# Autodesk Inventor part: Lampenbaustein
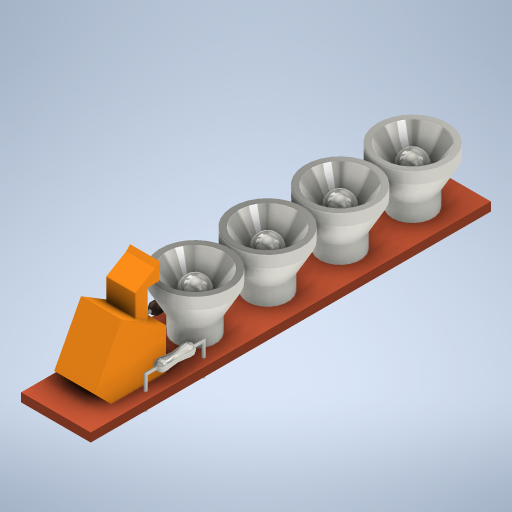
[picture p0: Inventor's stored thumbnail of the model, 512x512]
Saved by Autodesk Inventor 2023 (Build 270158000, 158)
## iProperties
Created: 2023-11
Part Number: Lampenbaustein
Material: Generisch
Document SubType Name: Modeling
Designer: Admin
Density: 1 g/cm^3
Appearance: Vorgabe
Author: Admin
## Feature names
1. Extrusion1
2. Extrusion2
3. Extrusion3
4. Extrusion4
5. Umdrehung1 [Revolution]
6. Extrusion5
7. Rechteckige Anordnung2 [Rectangular Pattern]
8. Umdrehung2 [Revolution]
9. Sweeping1
## Parameters: d0 = 12 mm, d1 = 69 mm, d2 = 1.5 mm, d3 = 0, d4 = 9 mm, d6 = 4 mm, d7 = 12.3 mm, d8 = 7 mm, d9 = 11.7 mm, d10 = 19 mm, d11 = 7 mm, d12 = 0, d13 = 3.8 mm, d16 = 2 mm, d17 = 2.5 mm, d18 = 2.2 mm, d19 = 1 mm, d20 = 4 mm, d21 = 15.5 mm, d22 = 3 mm, d23 = 5 mm, d24 = 0, d25 = 0.5 mm, d26 = 2.54 mm, d27 = 5 mm, d28 = 2.5 mm, d29 = 4 mm, d30 = 0, d31 = 3.5 mm, d32 = 2.25 mm, d33 = 6 mm, d34 = 1 mm, d35 = 1 mm, d36 = 4 mm, d37 = 2 mm, d38 = 9.5 mm, d39 = 10.5 mm, d40 = 3 mm, d41 = 90 deg, d45 = 0.25 mm, d46 = 2.54 mm, d47 = 4 mm, d48 = 0, d51 = 12.5 mm, d52 = 2.5 mm, d53 = 0.75 mm, d54 = 6.5 mm, d55 = 1 mm, d56 = 10.5 mm, d57 = 4.5 mm, d58 = 90 deg, d59 = -4.5 mm, d60 = 5.5 mm, d62 = 3 mm, d63 = 0.5 mm, d64 = 0, d65 = 0, d66 = 18.5 mm, d67 = 4.5 mm
